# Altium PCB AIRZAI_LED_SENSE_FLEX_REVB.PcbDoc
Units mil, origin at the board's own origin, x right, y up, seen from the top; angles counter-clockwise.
Board outline 2765.3 x 4393.69 mil, 2 copper layers (Top Layer, Bottom Layer); 62 components, 41 nets, 171 pads, 30 vias.
Unrouted connection lines stored in the file: 86.
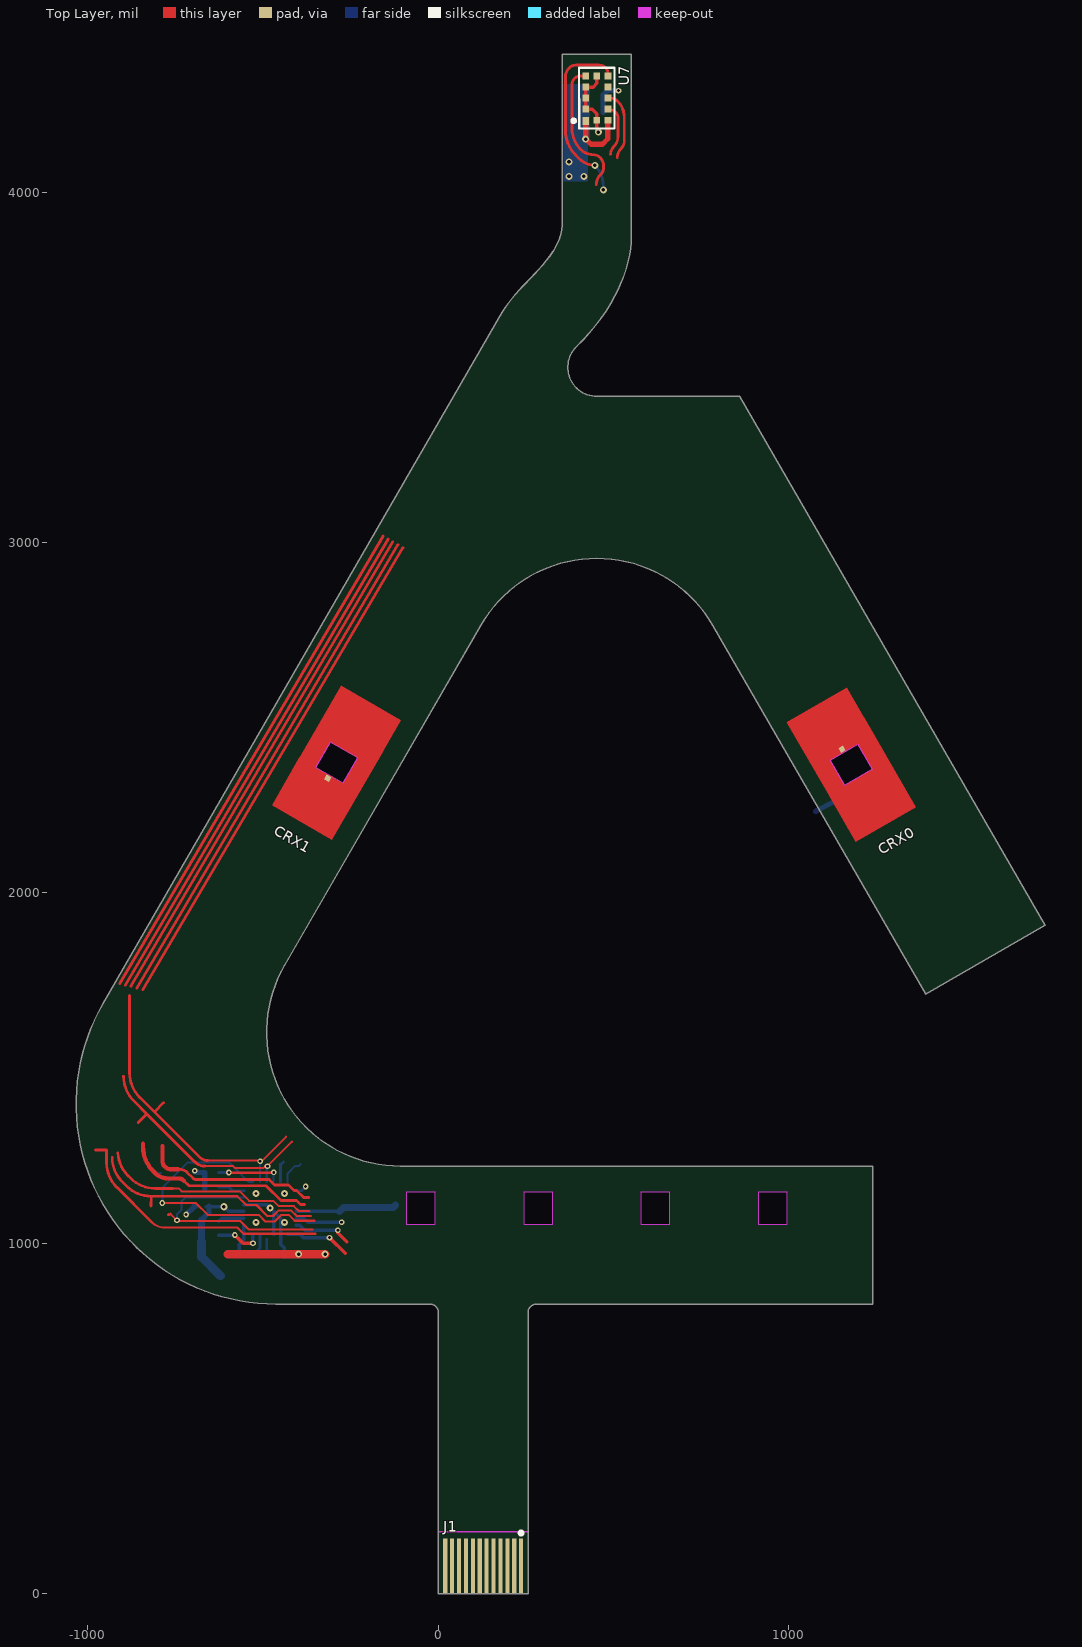
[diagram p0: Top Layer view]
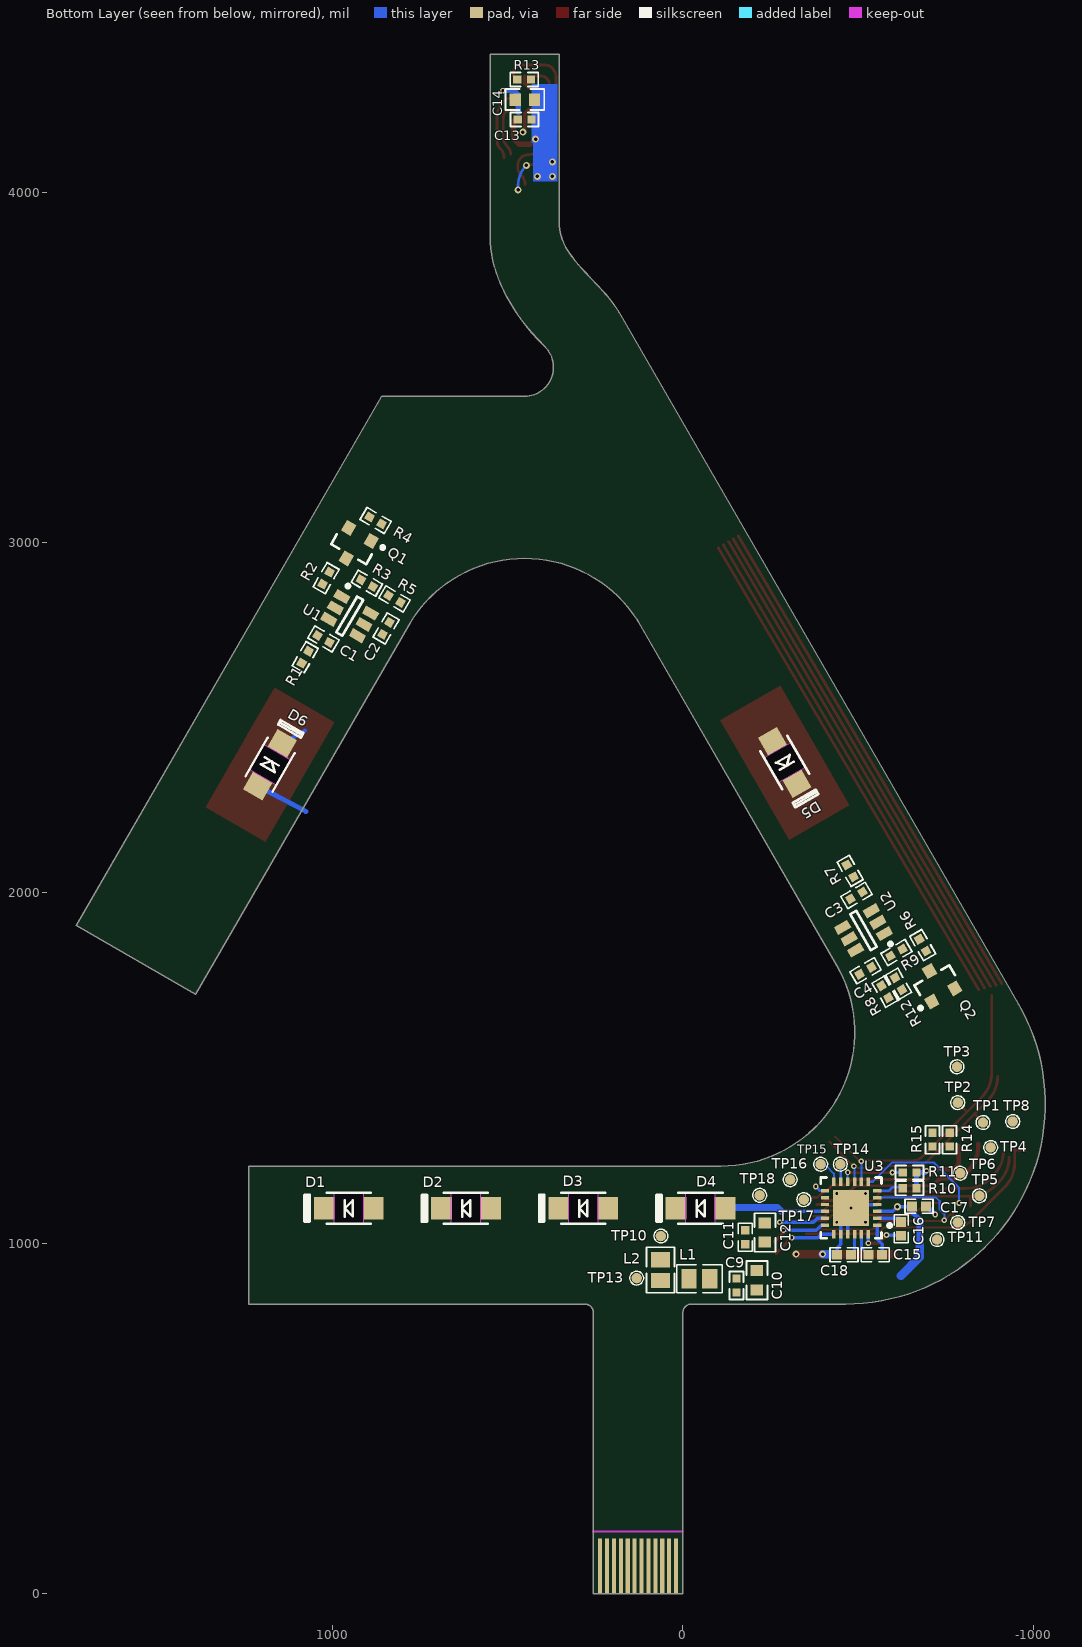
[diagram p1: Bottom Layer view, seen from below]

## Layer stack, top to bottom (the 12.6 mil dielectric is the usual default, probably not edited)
Top Solder: solder mask 0.4, Solder Resist, Dk 3.5
Top Layer: signal copper 1.4
Dielectric 1: dielectric 12.6, FR-4, Dk 4.8
Bottom Layer: signal copper 1.4
Bottom Solder: solder mask 0.4, Solder Resist, Dk 3.5

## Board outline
-462.98,826.77 -23.39,826.77 cw(c-23.88,802.89) 0,802.41 0,0 255.91,0 255.91,802.77 cw(c279.78,802.89) 279.66,826.77 1239.32,826.77 1239.36,826.74 1239.37,1220.44 -108.39,1220.47 cw(c-108.38,1602.36) -439.1,1793.32 121.28,2763.87 cw(c452,2572.92) 782.73,2763.85 1390.38,1711.31 1731.6,1907.71 860.08,3417.3 452.02,3417.31 cw(c452.02,3499.99) 394.16,3559.04 ccw(c-49.74,4012.89) 464.84,3641.1 ccw(c24.31,3959.43) 503.7,3703.33 ccw(c91.77,3922.61) 519.55,3736.13 ccw(c138.88,3902.12) 532.52,3769.79 ccw(c183.5,3887.15) 542.24,3804.11 ccw(c239.31,3875.17) 550.46,3874 550.46,3952.74 550.46,4393.69 353.61,4393.69 353.61,3952.75 353.61,3913.38 cw(c222.06,3913.41) 350.2,3883.68 cw(c204.05,3917.92) 340.75,3855.9 cw(c158.18,3938.86) 326.37,3829.65 cw(c73.79,3993.55) 308.19,3804.57 cw(c-93.59,4128.16) 287.35,3780.27 cw(c-627.68,4615.35) 264.96,3756.39 242.17,3732.54 ccw(c839.65,3165.01) 220.1,3708.36 ccw(c465.09,3488.64) 182.62,3657.48 -957.36,1683.09 ccw(c-462.98,1397.65)
cut-out: 912.59,1055.11 995.26,1055.11 995.26,1145.66 912.59,1145.66
cut-out: 577.94,1055.12 660.62,1055.12 660.62,1145.67 577.94,1145.67
cut-out: 243.3,1055.12 325.97,1055.12 325.97,1145.67 243.3,1145.67
cut-out: -91.36,1055.12 -8.68,1055.12 -8.68,1145.67 -91.36,1145.67
cut-out: 1159.59,2307.55 1118.49,2378.93 1196.97,2424.11 1238.06,2352.73
cut-out: -350.14,2359.11 -271.67,2313.93 -230.57,2385.31 -309.04,2430.49

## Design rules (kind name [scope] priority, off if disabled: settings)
Clearance Clearance_Board_Cutout_Electrodes [(InComponent('CRX0') OR InComponent('CRX1')) vs OnLayer('Multi-Layer')] p1: gap=0 ignorepadtopadclearanceinfootprint=FALSE
Clearance Clearance_Board_Cutout_Diodes [(InComponent('D1') OR InComponent('D2') OR InComponent('D3') OR InComponent('D4') OR InComponent('D5') OR InComponent('D6')) vs OnLayer('Multi-Layer')] p2: gap=0 ignorepadtopadclearanceinfootprint=FALSE
Clearance Clearance_Keepout [(OnLayer('Keep-Out Layer')) vs (InComponent('D1') OR InComponent('D2') OR InComponent('D3') OR InComponent('D4') OR InComponent('D5') OR InComponent('D6') OR InComponent('CRX0') OR InComponent('CRX1') OR InComponent('J1'))] p3: gap=0 ignorepadtopadclearanceinfootprint=FALSE
Clearance Clearance_GND_POLY_ELECTRODE [(InComponent('CRX0') OR InComponent('CRX1') OR InComponent('CRX2') OR InNet('NetCRX0_1') OR InNet('NetCRX1_1') OR InNet('NetCRX2_1') OR InNet('NetR4_2') OR InNet('NetR2_1') OR InNet('NetR1_1')) vs (InNet('GND') AND InPolygon)] p4: gap=30 ignorepadtopadclearanceinfootprint=FALSE
Clearance Clearance_POLYGON_KEEPOUT [(OnLayer('Keep-Out Layer')) vs (InNet('GND') AND InPolygon)] p5: gap=10 ignorepadtopadclearanceinfootprint=FALSE
Clearance Clearance_GND_POLY_REST [All vs (InNet('GND') AND InPolygon)] p6: gap=10 ignorepadtopadclearanceinfootprint=FALSE
Clearance [All] p7: gap=6 ignorepadtopadclearanceinfootprint=FALSE
MinimumSolderMaskSliver [All] p1: minsoldermaskwidth=1
PolygonConnect [All] p1: connectstyle=Direct reliefconductorwidth=10 reliefentries=4 polygonreliefangle="90 Angle" airgapwidth=10
RoomDefinition AIRZAI_LED_SENSE_FLEX_REVB [InComponentClass('AIRZAI_LED_SENSE_FLEX_REVB')] p1: confinementstyle=ConfineIn formatcopy=TRUE lockcomponents=FALSE outline -3892.14,-2713.97 10767.86,-2713.97 10767.86,6886.03 -3892.14,6886.03
RoutingVias [All] p1: holewidth=28 width=50 viastyle="Through Hole" minholewidth=8 minwidth=16 maxholewidth=28 maxwidth=50
SilkToSilkClearance [All] p1: silktosilkclearance=1
SilkToSolderMaskClearance [IsPad] p1: minsilkscreentomaskgap=2 clearancetoexposedcopper=TRUE
SolderMaskExpansion [All] p1: expansion=4
UnRoutedNet [All] p1: checkbadconnections=TRUE
Width [All] p1: maxlimit=100 minlimit=6 preferedwidth=10
26 further rules are at their usual default settings.

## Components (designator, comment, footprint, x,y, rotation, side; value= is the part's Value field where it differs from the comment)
C1 "22nF" 0402CAP 1025.94,2724.89 r210 bottom
C2 "0.1µF" 0402CAP 847,2755 r120 bottom
C3 "22nF" 0402CAP -495.16,1993.08 r330 bottom
C4 "0.1µF" 0402CAP -521.16,1778.08 r150 bottom
C9 "0.1µF" 0402CAP -153,880 r270 bottom
C10 "10µF" 0603 -211,895 r270 bottom
C11 "0.1µF" 0402CAP -178,1017.59 r90 bottom
C12 "10µF" 0603 -234,1031.37 r90 bottom
C13 "0.1µF" 0402CAP 452.01,4207.25 r0 bottom
C14 "4.7µF" 0603 451,4264 r180 bottom
C15 "CAP 1uF 16V 0402(1005)" CAPC0402(1005)60_M -548.79,967.64 r0 bottom value=1uF
C16 "CAP 1uF 16V 0402(1005)" CAPC0402(1005)60_M -622.66,1041.7 r270 bottom value=1uF
C17 "CAP 1uF 16V 0402(1005)" CAPC0402(1005)60_M -673.84,1105.87 r0 bottom value=1uF
C18 "CAP 1uF 16V 0402(1005)" CAPC0402(1005)60_M -459.79,967.64 r0 bottom value=1uF
CRX0 "CONTACT POINT 1" "CONTACT_POINT_1CM _SQ" 1178.28,2365.83 r300 top
CRX1 "CONTACT POINT 1" "CONTACT_POINT_1CM _SQ" -290.35,2372.21 r60 top
D1 "WHITE" LED1206_LTW-C230DS 953.93,1100.39 r0 bottom locked
D2 "WHITE" LED1206_LTW-C230DS 619.28,1100.4 r0 bottom locked
D3 "WHITE" LED1206_LTW-C230DS 284.63,1100.41 r0 bottom locked
D4 "WHITE" LED1206_LTW-C230DS -50.03,1100.42 r0 bottom
D5 "WHITE" LED1206_LTW-C230DS -290.35,2372.21 r240 bottom
D6 "WHITE" LED1206_LTW-C230DS 1178.28,2365.83 r120 bottom
J1 "FFC Pads" FFC_PADS 127.95,78.74 r0 top locked
L1 "CB2012T100KR" 0805 -47,899 r180 bottom value=10uH
L2 "CB2012T100KR" 0805 64,924 r90 bottom value=10uH
Q1 "NTR4003NT1G" SOT-23-3-NTR4003NT1G 941.1,2989 r300 bottom
Q2 "NTR4003NT1G" SOT-23-3-NTR4003NT1G -723.16,1743.08 r60 bottom
R1 "10k 0402(1005)" 0402 1077.94,2672.89 r300 bottom value=10k
R2 "100R 0402(1005)" 0402 1018.16,2898.37 r300 bottom value=100
R3 "Jumper 0402(1005)" 0402 902,2884 r30 bottom value=0R
R4 "DNP 0402(1005)" 0402 877,3063 r30 bottom value=DNP
R5 "DNP 0402(1005)" 0402 823,2839 r210 bottom value=DNP
R6 "100R 0402(1005)" 0402 -684.16,1851.08 r60 bottom value=100
R7 "10k 0402(1005)" 0402 -477.11,2063.08 r60 bottom value=10k
R8 "Jumper 0402(1005)" 0402 -576.26,1718.14 r240 bottom value=0R
R9 "DNP 0402(1005)" 0402 -609.01,1830.08 r330 bottom value=DNP
R10 "Jumper 0402(1005)" 0402 -646.68,1157.62 r0 bottom value=0R
R11 "Jumper 0402(1005)" 0402 -646.68,1202.62 r0 bottom value=0R
R12 "DNP 0402(1005)" 0402 -615.26,1740.95 r240 bottom value=DNP
R13 "10k 0402(1005)" 0402 453,4321 r0 bottom value=10k
R14 "Jumper 0402(1005)" 0402 -760.91,1296 r270 bottom value=0R
R15 "DNP 0402(1005)" 0402 -712,1296 r90 bottom value=DNP
TP1 "Test Point" TP_0.9MM -856.16,1344.94 r90 bottom
TP2 "Test Point" TP_0.9MM -784.16,1401.72 r90 bottom
TP3 "Test Point" TP_0.9MM -782,1504 r90 bottom
TP4 "Test Point" TP_0.9MM -878,1274 r90 bottom
TP5 "Test Point" TP_0.9MM -846,1136 r90 bottom
TP6 "Test Point" TP_0.9MM -791,1200.46 r90 bottom
TP7 "Test Point" TP_0.9MM -784.16,1060 r90 bottom
TP8 "Test Point" TP_0.9MM -941,1348 r90 bottom
TP10 "Test Point" TP_0.9MM 63,1021 r90 bottom
TP11 "Test Point" TP_0.9MM -725,1011 r90 bottom
TP13 "Test Point" TP_0.9MM 132,901 r90 bottom
TP14 "Test Point" TP_0.9MM -449,1226 r90 bottom
TP15 "Test Point" TP_0.9MM -393,1226 r90 bottom
TP16 "Test Point" TP_0.9MM -306,1181.96 r90 bottom
TP17 "Test Point" TP_0.9MM -345,1125 r90 bottom
TP18 "Test Point" TP_0.9MM -219,1137.41 r90 bottom
U1 "AT42QT1010-TSHR" SOT-23-6-AT42QT1010-TSHR 950.94,2789.89 r210 bottom
U2 "AT42QT1010-TSHR" SOT-23-6-AT42QT1010-TSHR -515.16,1893.08 r330 bottom
U3 "LP55231SQE/NOPB" WQFN-24-LP55231SQE/NOPB -479.85,1101.25 r0 bottom value="IC LED DRIVER RGLTR DIM 24WQFN"
U7 "VL53L0CXV0DH/1" VL53L0X 452,4268 r270 top

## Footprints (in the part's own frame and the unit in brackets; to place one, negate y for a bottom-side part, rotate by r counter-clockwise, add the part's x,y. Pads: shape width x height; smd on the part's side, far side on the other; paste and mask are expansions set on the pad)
0402 [mm] "Chip Resistor, Body 1.1x0.5mm, IPC High Density"
  rect 0.6x0.6 smd: 1(-0.5,0) 2(0.5,0)
  silkscreen extent -1.02,-0.51 1.02,0.51, body extent -0.5,-0.25 0.5,0.25, height 0.27
0402CAP [mm] "Chip Capacitor, Body 1.1x0.5mm, IPC High Density"
  rect 0.6x0.6 smd: 1(-0.5,0) 2(0.5,0)
  silkscreen extent -1.02,-0.51 1.02,0.51, body extent -0.5,-0.3 0.5,0.3, height 0.19
0603 [mm] "Chip Resistor, Body 1.6x0.8mm, IPC High Density"
  rect 0.8x0.9 smd: 1(-0.7,0) 2(0.7,0)
  silkscreen extent -1.4,-0.76 1.4,0.76, body extent -0.8,-0.41 0.8,0.4, height 0.37
0805 [mm] "Chip Resistor, Body 2.0x1.3mm, IPC High Density"
  rect 1.1x1.4 smd: 1(-0.75,0) 2(0.75,0)
  silkscreen extent -1.65,-1.02 1.65,1.02, body extent -1.02,-0.64 0.98,0.62, height 0.47
CAPC0402(1005)60_M [mm] "Chip Capacitor, Body 1.0x0.5mm, Height 0.6mm, IPC Low Density"
  rect 0.72x0.72 smd: 1(-0.5,0) 2(0.5,0)
  silkscreen extent -1.02,-0.51 1.02,0.51, body extent -0.55,-0.3 0.55,0.3, height 0.6
"CONTACT_POINT_1CM _SQ" [mm]
  rect 0.4x0.4 smd paste-2 mask-2: 1(-1.312,-0.018)
  Top Layer region: -2.48,2.5 -1.05,1.15 1.05,1.15 1.05,-2.5 5,-2.5 5,2.5
  Top Layer region: 2.48,-2.5 1.05,-1.15 -1.05,-1.15 -1.05,2.5 -5,2.5 -5,-2.5
FFC_PADS [mm] "(0.50mm"
  rect 0.3x4 smd: 1(2.75,0) 2(2.25,0) 3(1.75,0) 4(1.25,0) 5(0.75,0) 6(0.25,0) 7(-0.25,0) 8(-0.75,0) 9(-1.25,0) 10(-1.75,0) 11(-2.25,0) 12(-2.75,0)
  rect 0.3x4 smd far side: 1(2.75,0) 2(2.25,0) 3(1.75,0) 4(1.25,0) 5(0.75,0) 6(0.25,0) 7(-0.25,0) 8(-0.75,0) 9(-1.25,0) 10(-1.75,0) 11(-2.25,0) 12(-2.75,0)
  silkscreen extent 2.63,2.29 2.87,2.54
LED1206_LTW-C230DS [mm] "Chip Capacitor, Body 3.2x1.6mm, IPC High Density"
  rect 1.5x1.6 smd paste-0.1 mask+0.07: 1(1.775,0) 2(-1.775,0)
  silkscreen extent -1.6,-1.13 3.19,1.13, body extent -1.63,-0.8 1.63,0.8, height 0.31
SOT-23-3-NTR4003NT1G [mm] "SOT23, 3-Leads, Body 2.92x1.3mm, Pitch 0.95mm"
  rect 0.9x0.8 smd: 1(-1,0.95) 2(-1,-0.95) 3(1,0)
  silkscreen extent -1.12,-1.46 0.65,2.02, body extent -0.65,-1.46 0.65,1.46, height 1.11
SOT-23-6-AT42QT1010-TSHR [mm] "SOT23, 6-Leads, Body 2.9x1.6mm, Pitch 0.95mm, Lead Span 2.8mm, IPC Medium Density"
  rect 1.1x0.65 smd: 1(-1.2,0.95) 2(-1.2,0) 3(-1.2,-0.95) 4(1.2,-0.95) 5(1.2,0) 6(1.2,0.95)
  silkscreen extent -1.32,-1.5 0.25,1.95, body extent -0.88,-1.5 0.88,1.5, height 1.45
TP_0.9MM [mm] "0.9MM DIA TESTPOINT"
  round 0.75 smd paste-5 mask+0.05: 1(0,0)
  silkscreen extent -0.5,-0.5 0.5,0.5
VL53L0X [mm]
  rect 0.58x0.5 smd: 1(1.64,-0.8)
  rect 0.5x0.5 smd: 2(0.8,-0.8) 3(0,-0.8) 4(-0.8,-0.8) 5(-1.6,-0.8) 6(-1.6,0) 7(-1.6,0.8) 8(-0.8,0.8) 9(0,0.8) 10(0.8,0.8) 11(1.6,0.8) 12(1.6,0)
  silkscreen extent -2.2,-1.79 2.2,1.3, body extent -2.2,-1.3 2.2,1.3, height 3.72
WQFN-24-LP55231SQE/NOPB [mm] "QFN, 24-Leads, Body 3.97x3.97mm, Pitch 0.50mm, Thermal Pad 2.60x2.60mm, IPC Medium Density"
  rect 0.6x0.25 smd: 1(-1.9,1.25) 2(-1.9,0.75) 3(-1.9,0.25) 4(-1.9,-0.25) 5(-1.9,-0.75) 6(-1.9,-1.25) 13(1.9,-1.25) 14(1.9,-0.75) 15(1.9,-0.25) 16(1.9,0.25) 17(1.9,0.75) 18(1.9,1.25)
  rect 0.25x0.6 smd: 7(-1.25,-1.9) 8(-0.75,-1.9) 9(-0.25,-1.9) 10(0.25,-1.9) 11(0.75,-1.9) 12(1.25,-1.9) 19(1.25,1.9) 20(0.75,1.9) 21(0.25,1.9) 22(-0.25,1.9) 23(-0.75,1.9) 24(-1.25,1.9)
  rect 2.6x2.6 smd: 25(0,0)
  silkscreen extent -2.92,-2.2 2.2,2.2, body extent -2.01,-2.01 2.01,2.01, height 0.8

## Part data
C1 C3: library part C0402-100n, "Capacitor, X7R, ±10%", Case/Package=0402, Case Code (Metric)=1005, Dielectric=X7R, Manufacturer=TDK, Manufacturer Part Number=CGA2B2X7R1E223K050BA, Max Operating Temperature=125°C, Min Operating Temperature=-55°C, Package Quantity=1, Ratings=AEC-Q200, Supplier Part Number 1=445-5609-1-ND, Tolerance=10%, Voltage Rating=25V
C2 C4 C9 C11 C13: library part C0402-100n, "Capacitor, X7R, ±10%", Case-EIA=0402, Case-Metric=1005, Manufacturer=TDK, Manufacturer Part Number=C1005X7R1C104K, Rated Voltage="16 V", Supplier Part Number 1=445-4952-2-ND, Tolerance=±20%
C10 C12: library part C0402-100n, "Capacitor, X7R, ±10%", Case-EIA=0603, Case-Metric=1608, Manufacturer=MURATA, Manufacturer Part Number=GRM188R60J106ME47D, Rated Voltage="6.3 V", Supplier Part Number 1=490-3896-6-ND, Tolerance=±20%
C14: library part "C0603-1µ0 X7R", "Capacitor, X7R, ±10%", Case-EIA=0402, Case-Metric=1005, Manufacturer=TDK, Manufacturer Part Number=C1005X5R0J475M, Rated Voltage="6.3 V", Supplier Part Number 1=445-7395-2-ND, Tolerance=±20%
C15 C16 C17 C18: library part CAP, "CAP 1uF 16V ±10% 0402 (1005 Metric) Thickness 0.6mm SMD", Case-EIA=0402, Case-Metric=1005, Manufacturer="Taiyo Yuden", Manufacturer Part Number=JMK105C6105KV-F, Rated Voltage="6.3 V", Supplier Part Number 1=587-3381-1-ND, Tolerance=±10%
CRX0 CRX1: library part WIRE_POINT
D1 D2 D3 D4 D5 D6: library part LED_LTW-C230DS, Case-EIA=1206, Case-Metric=3216, Manufacturer=LITEON, Manufacturer Part Number=LTW-C230DS, Supplier Part Number 1=160-2221-1-ND
J1: library part FFC_PADS, "0.5 mm Pitch FFC Pads"
L1 L2: "Inductor, 10 µH, 0.5A, 0.65 ohm, SMD", Case/Package=0805, Case Code (Metric)=2012, Current Rating=520mA, DC Resistance (DCR)=500mR, Inductance=10uH, Inductance Tolerance=10%, Manufacturer="Taiyo Yuden", Max DC Current=200mA, Max Operating Temperature=105°C, Min Operating Temperature=-40°C, Package Quantity=3000, Self Resonant Frequency=32MHz, Supplier Part Number 1=587-2452-1-ND, Test Frequency=2.52MHz, Value1="0.65 ohm", Value2=0.5A, ValueDisplayed=10µH
Q1 Q2: "N-Channel 30V 500mA (Ta) 690mW (Ta) Surface Mount SOT-23-3 (TO-236)", Case/Package=SOT-23-3, Continuous Drain Current (ID)=500mA, Drain to Source Breakdown Voltage=30V, Drain to Source Resistance=1R, Gate to Source Voltage (Vgs)=20V, Input Capacitance=21pF, Manufacturer="ON Semiconductor", Max Operating Temperature=150°C, Max Power Dissipation=690mW, Min Operating Temperature=-55°C, Package Quantity=1, Supplier Part Number 1=NTR4003NT1GOSCT-ND, Threshold Voltage=1.4V
R1 R7 R13: library part RES, "10k 0.063W 1% 0402 (1005 Metric)  SMD", Case-EIA=0402, Case-Metric=1005, Manufacturer=Yageo, Manufacturer Part Number=RC0402FR-0710KL, Power=0.063W, Supplier Part Number 1=311-10.0KLRCT-ND, Tolerance=None
R2 R6: library part RES, "100 0.063W 1% 0402 (1005 Metric)  SMD", Case-EIA=0402, Case-Metric=1005, Manufacturer=Yageo, Manufacturer Part Number=RC0402FR-07100RL, Power=None, Supplier Part Number 1=311-100LRCT-ND
R3 R8 R10 R11 R14: library part RES, "Jumper 0402 (1005 Metric)", Case-EIA=0402, Case-Metric=1005, Manufacturer=Panasonic, Manufacturer Part Number=ERJ-2GE0R00X, Power=None, Supplier Part Number 1=P0.0JCT-ND
R4 R5 R9 R12 R15: library part RES, "DNP", Case-EIA=0402, Case-Metric=1005, Power="0.0625 W", Tolerance=None
U1 U2: "One-channel Touch Sensor IC with Reset Timer, -40° to +85° C, 6-pin SOT23", Supplier Part Number 1=AT42QT1010-TSHRCT-ND
U3: "Imported", Case-EIA=24-WQFN, Manufacturer=TI, Supplier Part Number 1=296-39059-1-ND, Tolerance=None
U7: library part VL53L0X, Case-EIA=LGA12, Manufacturer=ST, Supplier Part Number 1=497-16538-1-ND, Tolerance=None

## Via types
v1: diameter 16, hole 8, Top Layer to Bottom Layer, tented both sides, 15 vias
v2: diameter 20, hole 10, Top Layer to Bottom Layer, tented both sides, 10 vias
v3: diameter 20, hole 8, Top Layer to Bottom Layer, 5 vias

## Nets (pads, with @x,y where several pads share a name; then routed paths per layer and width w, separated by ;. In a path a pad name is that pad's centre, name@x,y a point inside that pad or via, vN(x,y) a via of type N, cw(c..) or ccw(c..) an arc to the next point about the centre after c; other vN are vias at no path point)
3V3: C2.1 C4.1 C11.1 C12.1 C13.1 C14.2 D5.2 D6.2 L2.2 R3.2 R8.2 R13.1 R14.1 TP10.1 U1.5 U2.5 U7.1 U7.11 | length 177.6
  Top Layer w15: U7.1 v2(420.5,4151.32) 435.39,4136.43 467.89,4136.43 483.5,4152.04 U7.11@483.5,4201.86
  other v2: 372.74,4045 415.06,4045 372.74,4086
+5V: C9.1 C10.1 C17.2 L1.2 TP11.1 U3.3 | length 344.2
  Bottom Layer w10: C17.2@-662.42,1104.41 -654.16,1104.41 -611.85,1104.41 -598.85,1091.41 U3.3
  Bottom Layer w15: -676.91,983.46 -675.91,982.46 ; -675.91,1067.19 -654.16,1088.94 -654.16,1104.41 C17.2
  Bottom Layer w20: -675.91,1005.08 -675.91,1067.19
  Bottom Layer w25: -675.91,1005.08 -675.91,982.46 -675.91,961.58 -621.97,907.64
  other v2: -612.13,1104.69
CAP1_TOUCH_OUT: J1.6 Q1.1 R4.1 TP5.1 U1.1
CAP2_TOUCH_OUT: J1.8 Q2.1 R9.1 TP3.1 U2.1
EN: J1.4 R14.2 R15.1 TP7.1 U3.5 | length 676.1
  Top Layer w6: -771.79,1081.46 -769.83,1083.43 -767.86,1081.46 -764.7,1084.62 -746.35,1066.27 v1(-745.79,1066.27) ; v1@-746.35,1063.64 -564.69,1063.64 -540.68,1039.62 -358.68,1039.62
  Bottom Layer w6: v1(-745.79,1066.27) -745.79,1083.49 -732.82,1096.46 -732.82,1120.42 -722.45,1130.78 U3.5
GND: C2.2 C4.2 C9.2 C10.2 C11.2 C12.2 C13.2 C14.1 C17.1 C18.2 D1.1 D2.1 D3.1 D4.1 J1.1 J1.2 Q1.2 Q2.2 R4.2 R5.2 R9.2 R10.1 R11.1 R12.2 R15.2 U1.2 U2.2 U3.4 U3.20 U3.21 U3.25 U7.2 U7.3 U7.4 U7.6 U7.12 | length 1190.2
  Top Layer w10: U7.6 452,4310 441.5,4299.5 U7.4 U7.3 U7.2 439.49,4236.5 452,4223.99 U7.12 452,4175.5 v2(456.5,4171)
  Top Layer w25: -600.79,969.46 v2(-398.79,969.46) v2(-323.16,969.46)
  Bottom Layer w10: U3.4 -489.69,1111.09 v3(-479.85,1101.25) U3.25@-470.01,1091.41 ; U3.21 U3.25@-470.01,1091.41 ; C18.2 -440.11,987.78 -450.32,997.99 U3.20 -450.32,1071.72 U3.25@-470.01,1091.41
  Bottom Layer w15: v1(-719.79,1082.46) -696.39,1105.87 C17.1 ; v1(-695.09,1207.46) -690.25,1202.62 R11.1 R10.1 ; 470.18,4227.5 470.18,4277.62 478.05,4285.5 482.05,4289.5 v1(514,4289.5) ; 1076.66,2232.8 1213.22,2305.31
  Bottom Layer w25: C18.2 -438.28,969.46 v2(-398.79,969.46)
  other v3: -520.79,1060.31 -438.9,1060.31 -520.79,1142.2 -438.9,1142.2
INT: J1.5 TP6.1 U3.7 | length 832.9
  Top Layer w6: v1(-787.79,1115.46) -692.35,1115.46 -658.51,1081.62 -512.79,1081.62 -493.63,1062.46 -466.79,1062.46 -447.63,1081.62 -426.68,1081.62 -409.68,1064.62 -353.68,1064.62
  Bottom Layer w6: TP6.1@-798,1200.46 TP6.1 ; v1(-787.79,1115.46) -787.72,1115.54 -787.72,1158.49 -714.75,1231.46 -597.46,1231.46 -542.06,1176.05 U3.7
NetC1_1: C1.1 R1.1 U1.3
NetC1_2: C1.2 U1.4
NetC3_1: C3.1 R7.1 U2.3
NetC3_2: C3.2 U2.4
NetC15_1: C15.1 U3.1 | length 90.1
  Bottom Layer w10: C15.1 -568.48,997.78 -554.65,1011.61 U3.1
NetC15_2: C15.2 U3.23 | length 67
  Bottom Layer w8: C15.2 -509.38,987.37 U3.23
NetC16_1: C16.1 U3.2 | length 75.2
  Bottom Layer w10: C16.1@-626.39,1063.31 -617.98,1071.72 U3.2
NetC16_2: C16.2 U3.24 | length 135.8
  Top Layer w10: v1(-580.68,1023.94) -557.37,1000.62 v1(-529.06,1000.62) v1@-529.06,997.62
  Bottom Layer w10: C16.2@-626.39,1023.94 v1(-580.68,1023.94) ; v1(-529.06,1000.62) U3.24
NetC18_1: C18.1 U3.22 | length 47.5
  Bottom Layer w8: -489.69,1012.12 -489.69,974.85 C18.1@-482.48,967.64
NetCRX0_1: CRX0.1 R1.2
NetCRX1_1: CRX1.1 R7.2
NetD1_2: D1.2 U3.19 | length 187.2
  Top Layer w10: v1(-310.68,1016.62) -265.99,971.94
  Bottom Layer w10: U3.19 -394.67,1026.45 -384.84,1016.62 v1(-310.68,1016.62)
NetD2_2: D2.2 U3.18 | length 167.5
  Top Layer w10: v1(-286.68,1037.62) -286.68,1030.35 -261.27,1004.94
  Bottom Layer w10: U3.18 -395.26,1052.04 -380.84,1037.62 v1(-286.68,1037.62)
NetD3_2: D3.2 U3.17 | length 133.8
  Bottom Layer w10: U3.17 -383.78,1071.72 -372.36,1060.31 v1(-276,1060.31)
NetD4_2: D4.2 U3.16 | length 290.8
  Bottom Layer w10: U3.16 -281.59,1091.41
  Bottom Layer w20: -281.59,1091.41 -270,1103 -128.13,1103 D4.2@-121.67,1109.46
NetD5_1: D5.1 R6.2
NetD6_1: D6.1 R2.2
NetJ1_11: J1.11 L2.1 TP13.1
NetJ1_12: J1.12 L1.1
NetQ1_3: Q1.3 R2.1
NetQ2_3: Q2.3 R6.1
NetR3_1: R3.1 R5.1 U1.6
NetR8_1: R8.1 R12.1 U2.6
NetR10_2: R10.2 U3.6 | length 75.6
  Bottom Layer w8: R10.2@-626.11,1160.46 -597.52,1160.46 -587.52,1150.46 U3.6
NetR11_2: R11.2 U3.10 | length 186.4
  Top Layer w6: v1(-597.68,1202.37) -596.93,1201.62 v1@-471.01,1201.62
  Top Layer w8: v1@-471.01,1201.62 v1(-470.01,1202.62)
  Bottom Layer w6: U3.10 v1(-470.01,1202.62)
  Bottom Layer w8: R11.2 -597.93,1202.62 v1(-597.68,1202.37) ; v1(-470.01,1202.62) v1@-470.01,1204.62
NetTP14_1: TP14.1 U3.11 | length 59.6
  Bottom Layer w8: U3.11 TP14.1@-450.32,1226 ; TP14.1 TP14.1@-442.19,1232.81
NetTP15_1: TP15.1 U3.12 | length 72
  Bottom Layer w6: U3.12 -430.64,1199.36 -408.5,1221.5 -397.5,1221.5 TP15.1
NetTP16_1: TP16.1 U3.13 | length 31.2
  Bottom Layer w8: U3.13 -390.79,1150.46 v1(-378.79,1162.46)
NetTP17_1: TP17.1 U3.15
NetTP18_1: TP18.1 U3.14
SCL: J1.10 TP1.1 U3.9 U7.10 | length 864.9
  Top Layer w6: -665.79,1220.62 -585.68,1220.62 -580.68,1215.62 -498.68,1215.62 -493.93,1220.37 v1(-487.68,1220.37) ; v1@-487.81,1220.5 -418.02,1290.28
  Top Layer w8: -898.16,1477.26 ccw(c-798.16,1477.26) -868.88,1406.55 -832.16,1369.84 ; -856.16,1344.94 -832.16,1369.84 ; -665.79,1220.62 cw(c-665.79,1262.05) -695.09,1232.76 -832.16,1369.84 ; U7.10 486.16,4236.5 cw(c486.16,4209.16) 505.5,4228.5 cw(c488.6,4211.6) 512.5,4211.6 512.5,4158.47 cw(c471.53,4158.47) 500.5,4129.5 ccw(c522.22,4107.77) 491.5,4107.77
  Bottom Layer w6: U3.9 v1@-489.69,1216.36
SDA: J1.9 TP2.1 U3.8 U7.9 | length 1111.8
  Top Layer w6: -657.68,1236.46 -502.84,1236.46 -434.37,1304.94
  Top Layer w8: -881.37,1707.1 -881.16,1706.89 -881.16,1487.37 ccw(c-781.16,1487.37) -851.88,1416.66 -810.16,1374.94 ; -784.16,1401.72 -810.16,1374.94 ; -657.68,1236.46 cw(c-657.68,1270.26) -681.58,1246.36 -810.16,1374.94 ; U7.9 490.97,4268 cw(c490.97,4238.97) 511.5,4259.5 cw(c465.63,4213.63) 530.5,4213.63 530.5,4146.22 cw(c499.77,4146.22) 521.5,4124.5 ccw(c548.05,4097.94) 510.5,4097.94
  Bottom Layer w6: U3.8 -509.38,1229.93 v1@-508.68,1230.62
  other v1: -508.68,1234.62
TOFINT: J1.7 TP4.1 U7.7 | length 1161.8
  Top Layer w6: -756.79,1157.05 -741.11,1157.05 -732.52,1148.46 -566.6,1148.46 -539.76,1121.62 -470.79,1121.62 -455.63,1106.46 -412.79,1106.46 -398.79,1092.46 -367.79,1092.46
  Top Layer w8: -914.64,1258.42 ccw(c-814.79,1263.88) -885.5,1193.17 -878.67,1186.34 ccw(c-807.96,1257.05) -807.96,1157.05 -756.79,1157.05 ; v2(446.5,4076.5) cw(c446.5,4137.87) 403.11,4094.46 391.79,4105.79 cw(c462.5,4176.5) 362.5,4176.5 362.5,4327.94 cw(c400.05,4327.94) 373.5,4354.5 cw(c392.81,4335.18) 392.81,4362.5 458.47,4362.5 cw(c458.47,4335.59) 477.5,4354.61 cw(c463.01,4340.13) 483.5,4340.13 U7.7
  Bottom Layer w8: v2(446.5,4076.5) cw(c388.55,4018.56) 470.5,4018.56 v2(470.5,4006.5)
XSHUNT: J1.3 R13.2 TP8.1 U7.5 | length 1157.7
  Top Layer w6: -818.76,1061.43 ccw(c-780.47,1099.72) -780.47,1045.57 -573.9,1045.57 -555.96,1027.62 -350.68,1027.62
  Top Layer w8: -978.16,1266.94 -946.79,1266.94 -946.79,1230.88 ccw(c-846.79,1230.88) -917.5,1160.17 -818.76,1061.43 ; U7.5 404.18,4330.99 ccw(c404.18,4308.81) 388.5,4324.5 ccw(c406.41,4306.58) 381.07,4306.58 381.07,4182.87 ccw(c467.87,4182.87) 406.5,4121.5 ccw(c442.71,4157.71) 442.71,4106.5 cw(c442.71,4079.76) 461.62,4098.66 cw(c437.77,4074.81) 471.5,4074.81 471.5,4070.53 cw(c441.76,4070.53) 462.79,4049.5 461.61,4048.32 ccw(c488.42,4021.5) 450.5,4021.5
pads on no net: U7.8
copper on no net: | length 9191.4
  Top Layer w6: -751.79,1134.62 -573.68,1134.62 -548.68,1109.62 -518.95,1109.62 -487.79,1078.46 -471.79,1078.46 -456.63,1093.62 -419.65,1093.62 -404.17,1078.14 -363.17,1078.14
  Top Layer w8: -930.79,1245.88 ccw(c-830.79,1245.88) -901.5,1175.17 -890.24,1163.91 ccw(c-819.53,1234.62) -819.53,1134.62 ; -909.42,1741.9 -157.59,3018.58 ; -893.42,1736.9 -143.52,3010.3 ; -877.27,1733.9 -130.22,3002.47 ; -860.79,1727.9 -115.36,2993.72 ; -843.79,1723.9 -100.99,2985.25 ; -820.16,1106.46 -819.53,1134.62 ; -751.79,1134.62 -819.53,1134.62 ; -742.89,1211.46 -738.13,1211.46 cw(c-738.13,1181.29) -716.79,1202.62 -700.41,1186.24 ccw(c-691.68,1194.96) -691.68,1182.62 -482.79,1182.62 -467.21,1167.04 -427.37,1167.04 -411.79,1151.46 -404.79,1151.46 -384.11,1130.78 -369.68,1130.78 ; -725.79,1178.46 -711.95,1164.62 -491.79,1164.62 -449.36,1122.2 -405.11,1122.2 -404.68,1122.62 -393.15,1111.09 -381.68,1111.09
  Top Layer w12: -842.79,1284.46 -842.79,1276.72 ccw(c-742.79,1276.72) -813.5,1206.01 -807.96,1200.46 ccw(c-771.94,1236.48) -771.94,1185.54 -742.89,1185.54 cw(c-742.89,1161.37) -725.79,1178.46 ; -786.99,1277.8 -786.99,1233.17 ccw(c-769.25,1233.17) -781.79,1220.62 -779.4,1218.23 ccw(c-763.07,1234.56) -763.07,1211.46 -742.89,1211.46
  Bottom Layer w12: 1079.31,2463.32 1143.34,2426.35

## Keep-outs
Keep-Out Layer:
  lines w1.97: 0,177.4 cw(c1,177.4) 1,178.4 256.9,178.4 cw(c256.9,177.4) 257.9,177.4
  lines w5: 1,177.4 256.9,177.4

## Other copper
Top Layer:
  pour cut-out: 0,177.4 0,0 257.9,0 257.9,177.4
Bottom Layer:
  rectangle net 3V3: 378.77,4139.33 432.5,4308.5
  rectangle net 3V3: 357.5,4030 427.5,4308.5
  pour cut-out: -566.46,1187.46 cw(c-567.72,1186.21) -565.94,1186.21 -565.94,1014.03 -395.26,1014.03 -395.26,1187.86 -565.79,1187.86
  pour cut-out: 0,177.4 0,0 256.9,0 256.9,177.4
  pour cut-out: -209.33,2673.84 -156.33,2645.84 -157.33,2631.84 -160.33,2623.84 -164.33,2616.84 -170.33,2610.84 -187.33,2576.84 -185.33,2573.84 -68.33,2505.84 -289.33,2115.84 -290.33,2113.84 -327.33,2130.84 -512.33,2238.84 -496.33,2275.6 -291.33,2626.84 -290.33,2629.84 -248.33,2611.84 -233.33,2640.84 -230.57,2653.84 -224.33,2662.84 -218.33,2669.84

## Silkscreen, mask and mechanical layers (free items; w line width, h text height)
Mechanical 1:
  drawing of 2217 lines, arcs and shapes, not listed
  text "5" at 8156.7,4325.32 h137.8
  text "10,4" at -3062.72,4287.88 h137.8
  text "R2,1" at 506.89,3695.85 h137.8 r16.49
  text "R9,7" at 437.26,2998.71 h137.8 r295.83
  text "44,27" at 1708.78,2900.9 h137.8 r300
  text "44,27" at 6753.43,2783.45 h137.8 r60
  text "10" at 539.61,2504.29 h137.8 r30
  text "10" at -772.78,2485.04 h137.8 r330
  text "79,4" at 5488.08,2228.2 h137.8 r90
  text "65,8" at 5849.36,2115.99 h137.8 r90
  text "R9,7" at -1251.32,1934.38 h137.8 r352.12
  text "0,4" at -2643.99,1476.02 h137.8
  text "10" at 2083.24,1406.29 h137.8 r90
  text "R14,5" at -1410.39,1246.65 h137.8 r19.4
  text "57,74" at 7999.21,512.6 h137.8
Mechanical 2:
  lines w0.5: 648.1,3418.57 648.1,4095.74
Mechanical 3:
  lines w6: 518.57,4228.19 518.57,4247.19
Mechanical 4:
  lines w2: 1239.32,826.77 279.66,826.77 ccw(c279.78,802.89) 255.91,802.77 255.91,0 0,0 0,802.41 ccw(c-23.88,802.89) -23.39,826.77 -462.98,826.77 cw(c-462.98,1397.65) -957.36,1683.09 182.62,3657.48 cw(c465.09,3488.64) 220.1,3708.36 cw(c839.65,3165.01) 242.17,3732.54 264.96,3756.39 ccw(c-627.68,4615.35) 287.35,3780.27 ccw(c-93.59,4128.16) 308.19,3804.57 ccw(c73.79,3993.55) 326.37,3829.65 ccw(c158.18,3938.86) 340.75,3855.9 ccw(c204.05,3917.92) 350.2,3883.68 ccw(c222.06,3913.41) 353.61,3913.38 353.61,3952.75 353.61,4393.69 550.46,4393.69 550.46,3952.74 550.46,3874 cw(c239.31,3875.17) 542.24,3804.11 cw(c183.5,3887.15) 532.52,3769.79 cw(c138.88,3902.12) 519.55,3736.13 cw(c91.77,3922.61) 503.7,3703.33 cw(c24.31,3959.43) 464.84,3641.1 cw(c-49.74,4012.89) 394.16,3559.04 ccw(c452.02,3499.99) 452.02,3417.31 860.08,3417.3 1731.6,1907.71 1390.38,1711.31 782.73,2763.85 ccw(c452,2572.92) 121.28,2763.87 -439.1,1793.32 ccw(c-108.38,1602.36) -108.39,1220.47 1239.37,1220.44 1239.36,826.74
Mechanical 12:
  circle w0.5: c-266.51,2360.24 r98.43
  circle w0.5: c1190.18,2360.21 r98.43
  circle w0.5: c953.93,1100.37 r98.43
  circle w0.5: c619.28,1100.38 r98.43
  circle w0.5: c284.64,1100.39 r98.43
  circle w0.5: c-50.01,1100.39 r98.43
  circle w0.5: c-266.51,2360.24 r59.06
  circle w0.5: c1190.18,2360.21 r59.06
  circle w0.5: c953.93,1100.37 r59.06
  circle w0.5: c619.28,1100.38 r59.06
  circle w0.5: c284.64,1100.39 r59.06
  circle w0.5: c-50.01,1100.39 r59.06
  circle w0.5: c-266.52,2360.24 r98.43
  circle w0.5: c1190.17,2360.21 r98.43
  circle w0.5: c953.92,1100.37 r98.43
  circle w0.5: c619.27,1100.38 r98.43
  circle w0.5: c284.63,1100.39 r98.43
  circle w0.5: c-50.02,1100.4 r98.43
  circle w0.5: c-266.52,2360.24 r59.06
  circle w0.5: c1190.17,2360.21 r59.06
  circle w0.5: c953.92,1100.37 r59.06
  circle w0.5: c619.27,1100.38 r59.06
  circle w0.5: c284.63,1100.39 r59.06
  circle w0.5: c-50.02,1100.4 r59.06
  lines w0.5: 3216.56,-822.41 3216.56,-842.1 3413.41,-842.1 3413.41,-822.41 ; 3316.56,4765.63 3316.56,4785.31 3513.41,4785.31 3513.41,4765.63 ; 3452.81,-822.41 3452.81,-842.1 3649.66,-842.1 3649.66,-822.41 ; 3552.81,4765.63 3552.81,4785.31 3749.66,4785.31 3749.66,4765.63 ; 3787.46,-822.41 3787.46,-842.1 3984.31,-842.1 3984.31,-822.41 ; 3887.46,4765.63 3887.46,4785.31 4084.31,4785.31 4084.31,4765.63 ; 3905.61,995.94 3925.29,995.94 ; 3905.61,995.98 3905.61,1192.76 3925.29,1192.79 ; 3905.61,2255.78 3925.29,2255.78 ; 3905.61,2255.81 3905.61,2452.6 ; 3905.61,2452.63 3925.29,2452.63 ; 4122.1,-822.41 4122.1,-842.1 4318.95,-842.1 4318.95,-822.41 ; 4222.1,4765.63 4222.1,4785.31 4418.95,4785.31 4418.95,4765.63 ; 4456.75,-822.41 4456.75,-842.1 4653.6,-842.1 4653.6,-822.41 ; 4556.75,4765.63 4556.75,4785.31 4753.6,4785.31 4753.6,4765.63 ; 4673.25,-822.41 4673.25,-842.1 4870.1,-842.1 4870.1,-822.41 ; 4773.25,4765.63 4773.25,4785.31 4970.1,4785.31 4970.1,4765.63 ; 6284.03,2804.23 cw(c6295.04,2746.21) 6295.04,2805.26 ; 6323.32,2694.36 ccw(c6295.04,2746.21) 6329.47,2698.23 ; 6351.17,2764.56 cw(c6295.04,2746.21) 6353.87,2741.01 ; 6489.53,1528.13 cw(c6531.29,1486.37) 6494.23,1532.35 ; 6489.53,1444.61 ccw(c6531.29,1486.37) 6494.23,1440.39 ; 6568.35,1440.39 ccw(c6531.29,1486.37) 6573.05,1444.61 ; 6568.35,1532.35 cw(c6531.29,1486.37) 6573.05,1528.13 ; 6824.18,1444.62 ccw(c6865.94,1486.38) 6828.88,1440.4 ; 6824.18,1528.14 cw(c6865.94,1486.38) 6828.88,1532.36 ; 6903,1440.4 ccw(c6865.94,1486.38) 6907.7,1444.62 ; 6903,1532.36 cw(c6865.94,1486.38) 6907.7,1528.14 ; 7067.97,2412.23 cw(c7078.98,2354.21) 7078.98,2413.26 ; 7107.26,2302.36 ccw(c7078.98,2354.21) 7113.42,2306.23 ; 7135.11,2372.56 cw(c7078.98,2354.21) 7137.81,2349.01 ; 7158.83,1444.63 ccw(c7200.58,1486.39) 7163.52,1440.41 ; 7158.82,1528.14 cw(c7200.58,1486.39) 7163.52,1532.36 ; 7237.65,1440.41 ccw(c7200.58,1486.39) 7242.34,1444.63 ; 7237.64,1532.37 cw(c7200.58,1486.39) 7242.34,1528.15 ; 7273.48,1052.61 ccw(c7315.24,1094.37) 7278.18,1048.39 ; 7273.48,1136.13 cw(c7315.24,1094.37) 7278.17,1140.35 ; 7352.3,1048.39 ccw(c7315.24,1094.37) 7357,1052.61 ; 7352.3,1140.35 cw(c7315.24,1094.37) 7356.99,1136.13 ; 7493.47,1444.64 ccw(c7535.23,1486.4) 7498.17,1440.42 ; 7493.47,1528.15 cw(c7535.23,1486.4) 7498.17,1532.37 ; 7572.29,1440.42 ccw(c7535.23,1486.4) 7576.99,1444.64 ; 7572.29,1532.37 cw(c7535.23,1486.4) 7576.99,1528.15 ; 7608.12,1052.62 ccw(c7649.88,1094.38) 7612.82,1048.4 ; 7608.12,1136.13 cw(c7649.88,1094.38) 7612.82,1140.35 ; 7686.94,1048.4 ccw(c7649.88,1094.38) 7691.64,1052.62 ; 7686.94,1140.36 cw(c7649.88,1094.38) 7691.64,1136.14 ; 7803.52,2774.63 cw(c7751.73,2746.24) 7806.77,2767.65 ; 7942.77,1052.63 ccw(c7984.53,1094.39) 7947.47,1048.41 ; 7942.77,1136.14 cw(c7984.53,1094.39) 7947.47,1140.36 ; 8021.59,1048.41 ccw(c7984.53,1094.39) 8026.29,1052.63 ; 8021.59,1140.37 cw(c7984.53,1094.39) 8026.28,1136.15 ; 8277.42,1052.63 ccw(c8319.17,1094.39) 8282.11,1048.41 ; 8277.41,1136.15 cw(c8319.17,1094.39) 8282.11,1140.37 ; 8356.23,1140.37 cw(c8319.17,1094.39) 8360.93,1136.15 ; 8356.23,1048.42 ccw(c8319.17,1094.39) 8360.93,1052.64 ; 8587.46,2382.63 cw(c8535.68,2354.24) 8590.71,2375.65
Drill Drawing:
  text "PWB, LED SENSE FLEX" at 7553.47,-3644.84 h157.48
  text "PWB-020218-001" at 7740.48,-3970.63 h127.95
  text "1" at 10165.68,-4029.68 h78.74
  text "1" at 9976.7,-4033.62 h78.74
Mechanical 17:
  text "PWA, LED SENSE FLEX" at 7596.1,-3719.43 h157.48
  text "PWA-020218-001" at 7790.1,-4010.43 h127.95
  text "1" at 9968.83,-4021.81 h59.06
  text "1" at 10157.8,-4021.81 h59.06
  text "NOTES: /  / 1. ALL ASSEMBLY MATERIALS TO BE RoHS COMPLIANT. /  / 2. MATERIAL: /           • FLEXIBLE METAL CLAD DIELECTRIC IAW                 /             IPC-4204/11 E1E2 O0/0 CU W7 T/T /           • STIFFENER IAW IPC-4203/1-E1E8M1 /  / 3. FINISH:  IMMERSION GOLD /  / ALL EXPOSED CONDUCTIVE PATTERN AREAS NOT COVERED WITH COVERLAY MATERIAL OR OTHER PLATING  / SHALL BE IMMERSION GOLD (0.000030-0.000090 mm) OVER ELECTROLESS NICKEL (0.001-0.006 mm). /  / 4. LEGEND SHALL BE WHITE, PERMANENT, ORGANIC, NON-CONDUCTIVE UV OR EPOXY TYPE INK APPLIED  / TO THE TOP SIDE OF THE BOARD. THERE SHALL BE NO LEGEND ON ANY SOLDERABLE COMPONENT LAND. /  / 5. ALL ASSEMBLY MATERIALS TO BE RoHS COMPLIANT. /  / 6. ANY LABELS OR COMPOSITION OF, APPLIED TO THE BOARD NEED TO BE APPROVIED BY AIRZAI /  / 7. MINIMUM TRACE WIDTHS: /           EXTERNAL: 0.203 mm  INTERNAL: N/A /  / 8. MINIMUM SPACE BETWEEN FEATURES: /          EXTERNAL: 0.15 mm  INTERNAL: N/A /  / 9. Overall Board Thickness: 0.1mm" at -3748,-4143 h78.74
Mechanical 18:
  lines w5: -4122.85,-1925.75 -3922.85,-1925.75 ; -4122.85,449.25 -3922.85,449.25 ; -4122.85,2824.25 -3922.85,2824.25 ; -1622.85,-4300.75 -1622.85,-4100.75 ; -1622.85,4999.25 -1622.85,5199.25 ; 877.15,-4300.75 877.15,-4100.75 ; 877.15,4999.25 877.15,5199.25 ; 3377.15,-4300.75 3377.15,-4100.75 ; 3377.15,4999.25 3377.15,5199.25 ; 5877.15,-4300.75 5877.15,-4100.75 ; 5877.15,4999.25 5877.15,5199.25 ; 6176.35,-3802.97 10676.35,-3802.97 ; 6176.35,-3561.23 7247.02,-3561.23 ; 6176.35,-3327.18 7247.02,-3327.18 ; 6176.35,-3116.35 7247.02,-3116.35 ; 6177.15,-4100.75 10677.15,-4100.75 ; 6802.14,-4103.95 6802.14,-2903.95 ; 7247.02,-4102.97 7247.02,-2902.97 ; 7247.02,-3436.04 10676.2,-3436.04 ; 7586.98,-2902.97 10676.35,-2902.97 ; 7676.35,-2902.97 6176.35,-2902.97 ; 8377.15,-4300.75 8377.15,-4100.75 ; 8377.15,4999.25 8377.15,5199.25 ; 10299.97,-4102.97 10299.97,-3802.97 ; 10677.15,-2900.75 10677.15,-4100.75 ; 10677.15,-1925.75 10877.15,-1925.75 ; 10677.15,449.25 10877.15,449.25 ; 10677.15,2824.25 10877.15,2824.25 ; 4776.35,-4102.97 6176.35,-4102.97 ; 4776.35,-4102.97 6176.35,-4102.97 ; 4776.35,-4102.97 4776.35,-2902.97 6176.35,-2902.97 ; 6176.35,-4102.97 10676.35,-4102.97 ; 6176.35,-4102.97 10676.35,-4102.97 ; 6176.35,-4102.97 6176.35,-2902.97 ; 10676.35,-4102.97 10676.35,-2902.97 ; 10676.35,-4102.97 10676.35,-2902.97 ; 10677.15,-4100.75 10677.15,4999.25 -3922.85,4999.25 -3922.85,-4100.75 10677.15,-4100.75 ; -4122.85,-4300.75 -4122.85,5199.25 10877.15,5199.25 10877.15,-4300.75 -4122.85,-4300.75
  text "1" at -2891.51,5069.25 h70
  text "2" at -395.85,5069.25 h70
  text "3" at 2093.49,5069.25 h70
  text "4" at 4600.16,5069.25 h70
  text "5" at 7099.15,5069.25 h70
  text "6" at 9604.15,5069.25 h70
  text "A" at -4047.85,3926.25 h70
  text "A" at 10752.15,3926.25 h70
  text "B" at -4047.85,1546.25 h70
  text "B" at 10752.15,1546.25 h70
  text "C" at -4047.85,-828.75 h70
  text "C" at 10752.15,-828.75 h70
  text "AIRZAI PROPRIETARY & CONFIDENTIAL" at 6332.27,-2792.09 h127.95
  text "DATE:" at 6832.65,-2965.17 h45
  text "ENGINEER:" at 6198.79,-2971.47 h45
  text "UNLESS OTHERWISE SPECIFIED" at 4875.96,-3032.1 h59.06
  text "05/13/19" at 6839.98,-3073.78 h59.06
  text "FD" at 6391.67,-3080.05 h78.74
  text "DIMENSIONS ARE IN MM" at 4998.01,-3158.08 h59.06
  text "PCB DESIGNER:" at 6194.86,-3179.86 h45
  text "DATE:" at 6820.84,-3181.71 h45
  text "D" at -4047.85,-3198.75 h70
  text "D" at 10752.15,-3198.75 h70
  text "AIRZAI" at 7537.98,-3236.97 h127.95
  text "TOLERANCES" at 5198.79,-3284.07 h59.06
  text "05/13/19" at 6839.98,-3288.35 h59.06
  text "DFM" at 6365.29,-3289.93 h78.74
  text "DATE:" at 6820.84,-3394.3 h45
  text "CHECK" at 6194.86,-3396.39 h45
  text "ANGULAR" at 5683.05,-3441.55 h59.06
  text "DECIMALS" at 4879.9,-3453.36 h59.06
  text "TITLE:" at 7298.8,-3499.77 h45
  text "FD" at 6431.04,-3513.12 h78.74
  text ".XX +/- .127MM" at 4832.65,-3610.84 h59.06
  text "+/-" at 5671.23,-3614.78 h59.06
  text "REL" at 6206.67,-3627.38 h45
  text "DATE:" at 6836.59,-3634.46 h45
  text "FD" at 6421.2,-3729.66 h78.74
  text ".XXX +/- .080MM" at 4820.84,-3772.26 h59.06
  text "REV:" at 10322.42,-3866.75 h45
  text "SCALE:" at 6842.1,-3867.53 h45
  text "DWG NO:" at 7293.28,-3875.41 h45
  text "SIZE" at 6206.67,-3878.56 h45
  text "B" at 6410.41,-4009.15 h120
  text "DO NOT SCALE DRAWING" at 4875.96,-4012.41 h70.87
  text "A" at 10406.09,-4028.31 h120
  text "1:1" at 6890.72,-4032.77 h120
  text "SHEET" at 9757.85,-4064.38 h45
  text "OF" at 10021.63,-4064.38 h45
  text "1" at -2891.51,-4230.75 h70
  text "2" at -395.85,-4230.75 h70
  text "3" at 2093.49,-4230.75 h70
  text "4" at 4600.16,-4230.75 h70
  text "5" at 7099.15,-4230.75 h70
  text "6" at 9604.15,-4230.75 h70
